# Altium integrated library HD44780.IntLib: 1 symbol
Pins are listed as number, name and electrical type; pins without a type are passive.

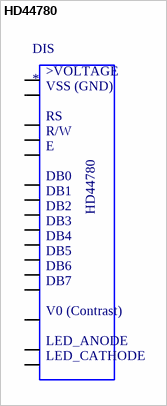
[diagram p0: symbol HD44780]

## HD44780
designator DIS
Character LCD Display Module Transflective 5 x 8 Dots STN - Super-Twisted Nematic LED - White Parallel 98.00mm x 60.00mm x 11.60mm; MF: Lumex Opto/Components; MP: HD44780
footprint 16026-16X2
pins: P$1 VSS (io), P$2 VDD (io), P$3 CONTRAST (io), P$4 RS (io), P$5 R/W (io), P$6 E (io), P$7 DB0 (io), P$8 DB1 (io), P$9 DB2 (io), P$10 DB3 (io), P$11 DB4 (io), P$12 DB5 (io), P$13 DB6 (io), P$14 DB7 (io), P$15 LED_A (io), P$16 LED_C (io)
